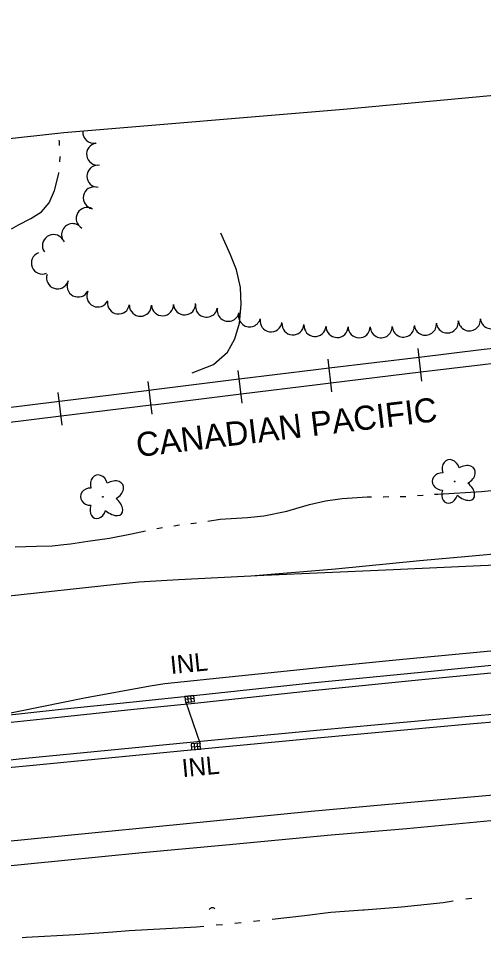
# Model space of a CAD drawing. Extents: x 589250 to 1188077, y 162953 to 363065.
# Drawn here: x 595418.8 to 595573.1, y 174942.7 to 175247.8 of the extents above; entities that cross this region are included whole.
import ezdxf

# ---------------------------------------------------------------- set-up
doc = ezdxf.new("R2010")
doc.units = 0
for name, color, linetype in [('E_DRN', 7, 'Continuous'), ('E_DRN_SS_UG', 7, 'Continuous'), ('E_DRN_Text', 7, 'Continuous'), ('E_DWY', 7, 'Continuous'), ('E_LAND_TreeLine_P', 7, 'Continuous'), ('E_LAND_Vegetation', 7, 'Continuous'), ('E_MAP_Limits', 7, 'Continuous'), ('E_RDWY', 7, 'Continuous'), ('E_RDWY_C_and_G', 7, 'Continuous'), ('E_RDWY_Gravel', 7, 'Continuous'), ('E_RR_P', 7, 'Continuous'), ('E_RR_Text', 7, 'Continuous'), ('E_WTR_FlowLine', 7, 'Continuous')]:
    doc.layers.add(name, color=color, linetype=linetype)

msp = doc.modelspace()

# ---------------------------------------------------------------- linework, layer by layer
at = {"layer": 'E_DRN'}
for p, q in [((595476.99, 175023.02), (595474.01, 175022.71)), ((595474.01, 175022.71), (595474.21, 175020.73)), ((595477.09, 175022.02), (595474.11, 175021.72)), ((595474.21, 175020.73), (595477.19, 175021.03)), ((595475.2, 175020.83), (595475, 175022.82)), ((595476.2, 175020.93), (595476, 175022.92)), ((595477.19, 175021.03), (595476.99, 175023.02)), ((595479.07, 175007.26), (595476.08, 175006.97)), ((595476.08, 175006.97), (595476.27, 175004.98)), ((595476.18, 175005.98), (595479.16, 175006.26)), ((595477.08, 175007.07), (595477.27, 175005.08)), ((595478.07, 175007.16), (595478.26, 175005.17)), ((595479.26, 175005.27), (595479.07, 175007.26)), ((595476.27, 175004.98), (595479.26, 175005.27))]:
    msp.add_line(p, q, dxfattribs=at)
msp.add_arc((595483.14, 174951.42), 1.2, 43.9785, 150.2387, dxfattribs=at)
at = {"layer": 'E_DRN_SS_UG'}
msp.add_line((595479.18, 175006.93), (595474.34, 175021.03), dxfattribs=at)
at = {"layer": 'E_DWY'}
for p, q in [((595489.17, 175169.26), (595485.92, 175176.48)), ((595491.17, 175164.27), (595489.17, 175169.26)), ((595492.49, 175158.49), (595491.17, 175164.27)), ((595492.68, 175152.78), (595492.49, 175158.49)), ((595492.1, 175146.61), (595492.68, 175152.78)), ((595490.55, 175141.39), (595492.1, 175146.61)), ((595488.21, 175137.01), (595490.55, 175141.39)), ((595483.51, 175132.94), (595488.21, 175137.01)), ((595476.43, 175130.17), (595483.51, 175132.94))]:
    msp.add_line(p, q, dxfattribs=at)
at = {"layer": 'E_LAND_TreeLine_P'}
for centre, start, end in [((595443.87, 175209.96), 174.0587, 281.0253), ((595445.09, 175202.74), 99.0805, 279.0805), ((595445.19, 175195.41), 90.5593, 270.5593), ((595443.99, 175188.2), 78.3032, 258.3032), ((595441.64, 175181.35), 60.85, 240.85), ((595436.79, 175175.99), 40.6639, 220.6639), ((595430.44, 175172.37), 35.0726, 215.0726), ((595426.79, 175166.57), 111.6093, 291.6093), ((595431.81, 175161.66), 161.6132, 341.6132), ((595438.61, 175158.96), 152.5711, 332.5711), ((595445.15, 175155.65), 154.4882, 334.4882), ((595452.01, 175153.32), 172.1574, 352.1574), ((595459.28, 175152.57), 181.0532, 1.0532), ((595466.61, 175152.73), 182.1621, 2.1621), ((595473.94, 175153), 182.1621, 2.1621), ((595481.19, 175152.27), 169.1646, 349.1646), ((595488.39, 175150.9), 169.1646, 349.1646), ((595495.48, 175149.05), 164.8525, 344.8525), ((595502.61, 175147.4), 171.3528, 351.3528), ((595509.87, 175146.39), 175.888, 355.888), ((595517.18, 175145.86), 175.888, 355.888), ((595553.78, 175146.27), 185.8389, 5.8389), ((595561.07, 175147.02), 185.8389, 5.8389), ((595568.37, 175147.73), 185.4126, 5.4126), ((595575.67, 175148.42), 185.4126, 5.4126), ((595524.49, 175145.5), 179.3434, 359.3434), ((595531.82, 175145.41), 179.3434, 359.3434), ((595539.15, 175145.44), 181.7519, 1.7519), ((595546.48, 175145.67), 181.7519, 1.7519)]:
    msp.add_arc(centre, 3.66, start, end, dxfattribs=at)
at = {"layer": 'E_LAND_Vegetation'}
for centre in [(595563.5, 175094.09), (595446.84, 175089)]:
    msp.add_circle(centre, 0.128, dxfattribs=at)
for centre, major_axis, ratio in [((595562.25, 175097.79), (1.02, -3.47), 0.782863), ((595566.43, 175096.06), (-3.65, -2.12), 0.691916), ((595445.59, 175092.71), (1.02, -3.47), 0.782863), ((595449.77, 175090.97), (-3.65, -2.12), 0.691916), ((595559.52, 175094.12), (3.45, -0.02), 0.832022), ((595442.85, 175089.04), (3.45, -0.02), 0.832022), ((595561.95, 175090.39), (1.2, 3.42), 0.716896), ((595566.16, 175091.54), (-3.57, 3.14), 0.560249), ((595449.49, 175086.46), (-3.57, 3.14), 0.560249), ((595445.29, 175085.3), (1.2, 3.42), 0.716896)]:
    msp.add_ellipse(centre, major_axis=major_axis, ratio=ratio, start_param=1.570796, end_param=4.712389, dxfattribs=at)
at = {"layer": 'E_MAP_Limits'}
for p, q in [((595854.42, 175247.77), (595526.63, 175217.54)), ((595526.63, 175217.54), (595433.93, 175209.82)), ((595433.93, 175209.82), (595347.24, 175200.01))]:
    msp.add_line(p, q, dxfattribs=at)
at = {"layer": 'E_RDWY'}
for p, q in [((595572.06, 175066.2), (595605.11, 175067.79)), ((595500.23, 175062.98), (595540.71, 175064.78)), ((595540.71, 175064.78), (595572.06, 175066.2)), ((595451.23, 175060.02), (595458.73, 175060.77)), ((595458.73, 175060.77), (595471.95, 175061.52)), ((595471.95, 175061.52), (595500.23, 175062.98)), ((595414.61, 175056.06), (595451.23, 175060.02)), ((595543.99, 175034.89), (595597.48, 175039.96)), ((595519.72, 175032.45), (595543.99, 175034.89)), ((595467.36, 175027.02), (595519.72, 175032.45)), ((595440.74, 175022.28), (595462.52, 175026.25)), ((595462.52, 175026.25), (595467.36, 175027.02)), ((595406.79, 175015.45), (595440.74, 175022.28)), ((595551.34, 174987.84), (595594.45, 174991.7)), ((595515.89, 174984.69), (595551.34, 174987.84)), ((595473.51, 174980.5), (595515.89, 174984.69)), ((595435.27, 174976.68), (595473.51, 174980.5)), ((595394.01, 174972.61), (595435.27, 174976.68))]:
    msp.add_line(p, q, dxfattribs=at)
at = {"layer": 'E_RDWY_C_and_G'}
for p, q in [((595552.42, 175030.85), (595601.54, 175035.64)), ((595552.66, 175028.36), (595601.78, 175033.15)), ((595515.97, 175027.24), (595552.42, 175030.85)), ((595478.03, 175023.12), (595515.97, 175027.24)), ((595516.23, 175024.75), (595552.66, 175028.36)), ((595478.29, 175020.64), (595516.23, 175024.75)), ((595432.95, 175018.51), (595456.85, 175020.97)), ((595456.85, 175020.97), (595478.03, 175023.12)), ((595411.77, 175016.25), (595432.95, 175018.51)), ((595433.21, 175016.02), (595457.1, 175018.49)), ((595457.1, 175018.49), (595478.29, 175020.64)), ((595618.26, 175020.43), (595566.95, 175015.94)), ((595618.47, 175017.93), (595567.17, 175013.45)), ((595412.09, 175013.77), (595433.21, 175016.02)), ((595566.95, 175015.94), (595518.92, 175011.55)), ((595567.17, 175013.45), (595519.15, 175009.06)), ((595518.92, 175011.55), (595475.78, 175007.44)), ((595519.15, 175009.06), (595476.02, 175004.96)), ((595475.78, 175007.44), (595421.13, 175002.15)), ((595476.02, 175004.96), (595421.38, 174999.66)), ((595421.13, 175002.15), (595375.44, 174997.42)), ((595421.38, 174999.66), (595375.7, 174994.93))]:
    msp.add_line(p, q, dxfattribs=at)
at = {"layer": 'E_RDWY_Gravel'}
for p, q in [((595568.1, 175069.34), (595591.1, 175071.32)), ((595523.95, 175065.15), (595551.92, 175067.86)), ((595551.92, 175067.86), (595568.1, 175069.34)), ((595497.37, 175062.84), (595523.95, 175065.15)), ((595547.59, 174978.97), (595585.88, 174982.51)), ((595522.57, 174976.79), (595547.59, 174978.97)), ((595487.64, 174973.52), (595522.57, 174976.79)), ((595459.88, 174970.91), (595487.64, 174973.52)), ((595433.08, 174968.32), (595459.88, 174970.91)), ((595403.89, 174965.46), (595433.08, 174968.32))]:
    msp.add_line(p, q, dxfattribs=at)
at = {"layer": 'E_RR_P'}
for p, q in [((595552.64, 175127.38), (595551.34, 175138.21)), ((595572.28, 175137.74), (595551.7, 175135.26)), ((595581.52, 175138.85), (595572.28, 175137.74)), ((595522.81, 175123.79), (595521.51, 175134.62)), ((595551.69, 175135.26), (595521.87, 175131.67)), ((595582.11, 175133.92), (595572.87, 175132.81)), ((595493.02, 175120.12), (595491.69, 175130.94)), ((595517.41, 175131.13), (595492.05, 175127.99)), ((595521.87, 175131.67), (595517.41, 175131.13)), ((595572.87, 175132.81), (595552.29, 175130.33)), ((595492.05, 175127.99), (595463.76, 175124.49)), ((595552.29, 175130.33), (595522.46, 175126.74)), ((595463.2, 175116.42), (595461.87, 175127.25)), ((595518.01, 175126.21), (595492.66, 175123.07)), ((595522.46, 175126.74), (595518.01, 175126.21)), ((595433.38, 175112.76), (595432.05, 175123.58)), ((595462.23, 175124.3), (595432.42, 175120.63)), ((595463.76, 175124.49), (595462.24, 175124.3)), ((595492.66, 175123.06), (595464.37, 175119.56)), ((595432.41, 175120.63), (595412.76, 175118.22)), ((595462.84, 175119.37), (595433.02, 175115.71)), ((595464.37, 175119.56), (595462.84, 175119.37)), ((595433.02, 175115.71), (595413.36, 175113.29))]:
    msp.add_line(p, q, dxfattribs=at)
at = {"layer": 'E_WTR_FlowLine'}
for p, q in [((595432.44, 175206.95), (595432.37, 175207.34)), ((595432.49, 175205.56), (595432.44, 175206.95)), ((595432.51, 175200.2), (595432.62, 175201.82)), ((595432.62, 175201.82), (595432.61, 175201.98)), ((595430.77, 175190.61), (595432.23, 175196.27)), ((595432.23, 175196.27), (595432.26, 175196.64)), ((595429.01, 175186.6), (595430.77, 175190.61)), ((595426.48, 175183.56), (595429.01, 175186.6)), ((595422.94, 175181.35), (595426.48, 175183.56)), ((595418.83, 175179.22), (595422.94, 175181.35)), ((595416.58, 175177.97), (595418.83, 175179.22)), ((595572.37, 175090.72), (595582.5, 175091.78)), ((595520.63, 175087.7), (595526.14, 175088.41)), ((595526.14, 175088.41), (595534.45, 175088.97)), ((595534.45, 175088.97), (595535.96, 175088.99)), ((595539.76, 175089.03), (595539.87, 175089.04)), ((595539.87, 175089.04), (595541.66, 175089.05)), ((595545.46, 175089.08), (595546.47, 175089.09)), ((595546.47, 175089.09), (595547.35, 175089.15)), ((595551.14, 175089.39), (595553.03, 175089.51)), ((595553.03, 175089.51), (595553.04, 175089.52)), ((595556.82, 175089.82), (595557.89, 175089.91)), ((595557.89, 175089.91), (595572.37, 175090.72)), ((595508.9, 175084.58), (595515.38, 175086.39)), ((595515.38, 175086.39), (595520.63, 175087.7)), ((595485.71, 175081.54), (595494.84, 175082.11)), ((595494.84, 175082.11), (595500.18, 175082.65)), ((595500.18, 175082.65), (595507.83, 175084.28)), ((595507.83, 175084.28), (595508.9, 175084.58)), ((595470.37, 175079.4), (595472.26, 175079.65)), ((595476.02, 175080.13), (595476.16, 175080.15)), ((595476.16, 175080.15), (595477.9, 175080.4)), ((595481.66, 175080.95), (595485.71, 175081.54)), ((595449, 175075.28), (595456.28, 175076.67)), ((595456.28, 175076.67), (595461.02, 175077.76)), ((595464.75, 175078.48), (595466.62, 175078.79)), ((595430.02, 175072.73), (595433.9, 175073.13)), ((595433.9, 175073.13), (595436.1, 175073.35)), ((595436.1, 175073.35), (595441.8, 175074.3)), ((595441.8, 175074.3), (595449, 175075.28)), ((595417.77, 175072.44), (595424.81, 175072.64)), ((595424.81, 175072.64), (595430.02, 175072.73)), ((595545.92, 174952.89), (595559.7, 174954.39)), ((595559.7, 174954.39), (595563.03, 174954.9)), ((595567.15, 174955.54), (595569.2, 174955.85)), ((595513.7, 174950.08), (595522.43, 174951.13)), ((595522.43, 174951.13), (595533.03, 174951.89)), ((595533.03, 174951.89), (595533.49, 174951.92)), ((595533.49, 174951.92), (595545.92, 174952.89)), ((595490.61, 174947.53), (595492.68, 174947.74)), ((595496.81, 174948.19), (595498.88, 174948.42)), ((595503.02, 174948.89), (595513.7, 174950.08)), ((595437.66, 174943.76), (595450.15, 174944.68)), ((595450.15, 174944.68), (595455.55, 174945.08)), ((595455.55, 174945.08), (595477.85, 174946.24)), ((595477.85, 174946.24), (595480.26, 174946.48)), ((595484.4, 174946.9), (595486.47, 174947.11)), ((595420.05, 174942.71), (595421.34, 174942.85)), ((595421.34, 174942.85), (595437.66, 174943.76))]:
    msp.add_line(p, q, dxfattribs=at)

# ---------------------------------------------------------------- texts
at = {"layer": 'E_DRN_Text'}
for rotation, p in [(5.7721, (595469.45, 175030.15)), (5.449, (595473.31, 174995.94))]:
    msp.add_text('INL', height=6, rotation=rotation, dxfattribs=at).set_placement(p)
at = {"layer": 'E_RR_Text'}
msp.add_text('CANADIAN PACIFIC', height=8, rotation=6.8307, dxfattribs=at).set_placement((595458.34, 175102.17))

doc.saveas('drawing.dxf')
